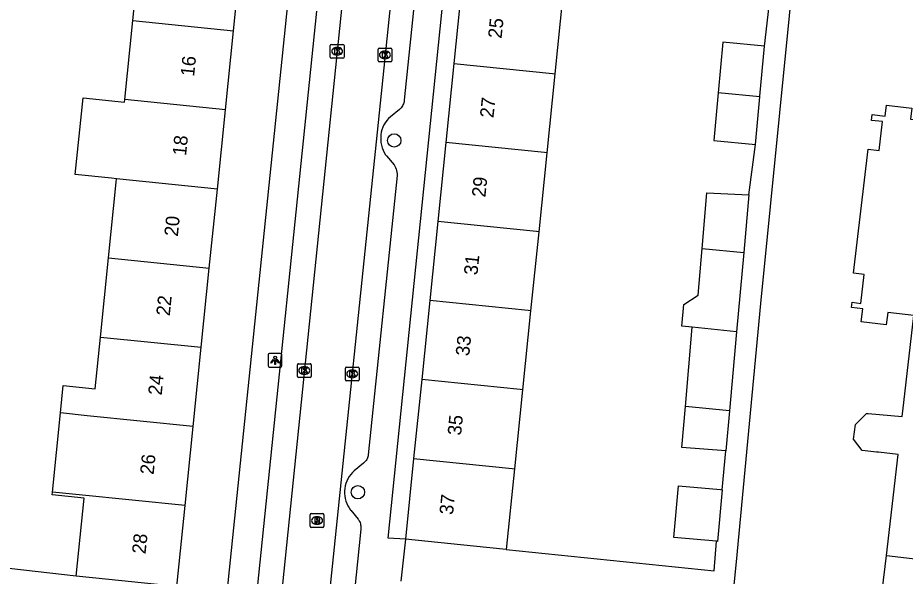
# Model space of a CAD drawing. Extents: x 160861 to 161308, y 384024 to 384878.
# Drawn here: x 161160.1 to 161224.9, y 384529.6 to 384570.4 of the extents above; entities that cross this region are included whole.
import ezdxf

# ---------------------------------------------------------------- set-up
doc = ezdxf.new("R2010")
doc.units = 0
for name, color, linetype in [('IMGEO_Boom', 7, 'Continuous'), ('IMGEO_Kolk', 7, 'Continuous'), ('IMGEO_Lichtpunt', 7, 'Continuous'), ('IMGEO_Pand', 7, 'Continuous'), ('IMGEO_Pand_nummerreeks', 7, 'Continuous'), ('IMGEO_Rijbaan_lokaal_open', 7, 'Continuous'), ('IMGEO_Rioolput', 7, 'Continuous'), ('IMGEO_Voetpad_open', 7, 'Continuous')]:
    doc.layers.add(name, color=color, linetype=linetype)

msp = doc.modelspace()

# ---------------------------------------------------------------- linework, layer by layer
at = {"layer": 'IMGEO_Boom'}
for centre in [(161187.565, 384561.474), (161184.912, 384535.755)]:
    msp.add_circle(centre, 0.489, dxfattribs=at)
at = {"layer": 'IMGEO_Kolk'}
for p, q in [((161182.898, 384567.567), (161182.898, 384568.419)), ((161182.973, 384568.493), (161183.825, 384568.493)), ((161183.386, 384568.273), (161183.411, 384568.273)), ((161183.899, 384568.419), (161183.899, 384567.567)), ((161186.386, 384567.299), (161186.386, 384568.151)), ((161186.461, 384568.225), (161187.313, 384568.225)), ((161186.874, 384568.005), (161186.899, 384568.005)), ((161187.387, 384568.151), (161187.387, 384567.299)), ((161183.825, 384567.493), (161182.973, 384567.493)), ((161183.409, 384567.713), (161183.384, 384567.713)), ((161186.897, 384567.445), (161186.872, 384567.445)), ((161187.313, 384567.225), (161186.461, 384567.225)), ((161180.495, 384544.229), (161180.495, 384545.081)), ((161180.57, 384545.155), (161181.422, 384545.155)), ((161180.983, 384544.935), (161181.008, 384544.935)), ((161181.496, 384545.081), (161181.496, 384544.229)), ((161183.996, 384543.983), (161183.996, 384544.835)), ((161184.071, 384544.909), (161184.923, 384544.909)), ((161184.484, 384544.689), (161184.509, 384544.689)), ((161184.997, 384544.835), (161184.997, 384543.983)), ((161181.422, 384544.155), (161180.57, 384544.155)), ((161181.006, 384544.375), (161180.981, 384544.375)), ((161184.507, 384544.129), (161184.482, 384544.129)), ((161184.923, 384543.909), (161184.071, 384543.909))]:
    msp.add_line(p, q, dxfattribs=at)
for points in [[(161182.898, 384567.567), (161182.898, 384568.419)], [(161182.973, 384568.493), (161183.825, 384568.493)], [(161183.219, 384568.193), (161183.342, 384568.193), (161183.342, 384568.042), (161183.472, 384568.193), (161183.636, 384568.193), (161183.49, 384568.042), (161183.643, 384567.793), (161183.491, 384567.793), (161183.406, 384567.957), (161183.342, 384567.89), (161183.342, 384567.793), (161183.219, 384567.793), (161183.219, 384568.193)], [(161183.899, 384568.419), (161183.899, 384567.567)], [(161186.386, 384567.299), (161186.386, 384568.151)], [(161186.461, 384568.225), (161187.313, 384568.225)], [(161187.387, 384568.151), (161187.387, 384567.299)], [(161183.825, 384567.493), (161182.973, 384567.493)], [(161186.707, 384567.925), (161186.83, 384567.925), (161186.83, 384567.774), (161186.96, 384567.925), (161187.124, 384567.925), (161186.978, 384567.774), (161187.131, 384567.525), (161186.979, 384567.525), (161186.894, 384567.689), (161186.83, 384567.622), (161186.83, 384567.525), (161186.707, 384567.525), (161186.707, 384567.925)], [(161187.313, 384567.225), (161186.461, 384567.225)], [(161180.495, 384544.229), (161180.495, 384545.081)], [(161180.57, 384545.155), (161181.422, 384545.155)], [(161180.816, 384544.855), (161180.939, 384544.855), (161180.939, 384544.704), (161181.069, 384544.855), (161181.233, 384544.855), (161181.087, 384544.704), (161181.24, 384544.455), (161181.088, 384544.455), (161181.003, 384544.619), (161180.939, 384544.552), (161180.939, 384544.455), (161180.816, 384544.455), (161180.816, 384544.855)], [(161181.496, 384545.081), (161181.496, 384544.229)], [(161183.996, 384543.983), (161183.996, 384544.835)], [(161184.071, 384544.909), (161184.923, 384544.909)], [(161184.997, 384544.835), (161184.997, 384543.983)], [(161181.422, 384544.155), (161180.57, 384544.155)], [(161184.317, 384544.609), (161184.44, 384544.609), (161184.44, 384544.458), (161184.57, 384544.609), (161184.734, 384544.609), (161184.588, 384544.458), (161184.741, 384544.209), (161184.589, 384544.209), (161184.504, 384544.373), (161184.44, 384544.306), (161184.44, 384544.209), (161184.317, 384544.209), (161184.317, 384544.609)], [(161184.923, 384543.909), (161184.071, 384543.909)]]:
    msp.add_lwpolyline(points, dxfattribs=at)
for centre, start, end in [((161182.975, 384568.417), 91.55205, 178.44795), ((161182.975, 384568.417), 91.55205, 178.44795), ((161183.823, 384568.417), 1.55205, 88.44795), ((161183.823, 384568.417), 1.55205, 88.44795), ((161186.463, 384568.149), 91.55205, 178.44795), ((161186.463, 384568.149), 91.55205, 178.44795), ((161187.311, 384568.149), 1.55205, 88.44795), ((161187.311, 384568.149), 1.55205, 88.44795), ((161182.975, 384567.569), 181.55205, 268.44795), ((161182.975, 384567.569), 181.55205, 268.44795), ((161183.823, 384567.569), 271.55205, 358.44795), ((161183.823, 384567.569), 271.55205, 358.44795), ((161186.463, 384567.301), 181.55205, 268.44795), ((161186.463, 384567.301), 181.55205, 268.44795), ((161187.311, 384567.301), 271.55205, 358.44795), ((161187.311, 384567.301), 271.55205, 358.44795), ((161180.572, 384545.079), 91.55205, 178.44795), ((161180.572, 384545.079), 91.55205, 178.44795), ((161181.42, 384545.079), 1.55205, 88.44795), ((161181.42, 384545.079), 1.55205, 88.44795), ((161184.073, 384544.833), 91.55205, 178.44795), ((161184.073, 384544.833), 91.55205, 178.44795), ((161184.921, 384544.833), 1.55205, 88.44795), ((161184.921, 384544.833), 1.55205, 88.44795), ((161180.572, 384544.231), 181.55205, 268.44795), ((161180.572, 384544.231), 181.55205, 268.44795), ((161181.42, 384544.231), 271.55205, 358.44795), ((161181.42, 384544.231), 271.55205, 358.44795), ((161184.073, 384543.985), 181.55205, 268.44795), ((161184.073, 384543.985), 181.55205, 268.44795), ((161184.921, 384543.985), 271.55205, 358.44795), ((161184.921, 384543.985), 271.55205, 358.44795)]:
    msp.add_arc(centre, 0.0765, start, end, dxfattribs=at)
for centre, major_axis, ratio, start_param, end_param in [((161183.385, 384567.993), (-0.387, 0.002), 0.722429, 4.712389, 7.853982), ((161183.41, 384567.993), (-0.39, 0.002), 0.717154, 1.570796, 4.712389), ((161186.873, 384567.725), (-0.387, 0.002), 0.722429, 4.712389, 7.853982), ((161186.898, 384567.725), (-0.39, 0.002), 0.717154, 1.570796, 4.712389), ((161180.982, 384544.655), (-0.387, 0.002), 0.722429, 4.712389, 7.853982), ((161181.007, 384544.655), (-0.39, 0.002), 0.717154, 1.570796, 4.712389), ((161184.483, 384544.409), (-0.387, 0.002), 0.722429, 4.712389, 7.853982), ((161184.508, 384544.409), (-0.39, 0.002), 0.717154, 1.570796, 4.712389)]:
    msp.add_ellipse(centre, major_axis=major_axis, ratio=ratio, start_param=start_param, end_param=end_param, dxfattribs=at)
at = {"layer": 'IMGEO_Lichtpunt'}
for p, q in [((161178.363, 384545.812), (161178.363, 384545.005)), ((161178.363, 384545.812), (161178.363, 384545.005)), ((161179.265, 384545.907), (161178.457, 384545.907)), ((161179.265, 384545.907), (161178.457, 384545.907)), ((161179.359, 384545.005), (161179.359, 384545.812)), ((161179.359, 384545.005), (161179.359, 384545.812)), ((161178.457, 384544.911), (161179.265, 384544.911)), ((161178.457, 384544.911), (161179.265, 384544.911))]:
    msp.add_line(p, q, dxfattribs=at)
for points in [[(161178.737, 384545.476), (161178.776, 384545.448), (161178.588, 384545.186), (161178.55, 384545.213), (161178.737, 384545.476)], [(161178.839, 384545.428), (161178.886, 384545.428), (161178.886, 384545.106), (161178.839, 384545.106), (161178.839, 384545.428)], [(161178.949, 384545.448), (161178.987, 384545.475), (161179.174, 384545.213), (161179.135, 384545.185), (161178.949, 384545.448)]]:
    msp.add_lwpolyline(points, dxfattribs=at)
msp.add_circle((161178.862, 384545.61), 0.0994, dxfattribs=at)
for centre, start, end in [((161178.457, 384545.812), 90, 180), ((161178.457, 384545.812), 90, 180), ((161179.265, 384545.812), 0, 90), ((161179.265, 384545.812), 0, 90), ((161178.457, 384545.005), 180, 270), ((161178.457, 384545.005), 180, 270), ((161179.265, 384545.005), 270, 0), ((161179.265, 384545.005), 270, 360)]:
    msp.add_arc(centre, 0.0946, start, end, dxfattribs=at)
at = {"layer": 'IMGEO_Pand'}
for points in [[(161168.464, 384570.248), (161169.053, 384576.035)], [(161175.822, 384569.5), (161176.41, 384575.287)], [(161192.519, 384572.886), (161191.929, 384567.109)], [(161199.89, 384572.134), (161199.301, 384566.357)], [(161167.876, 384564.461), (161168.464, 384570.248)], [(161168.464, 384570.248), (161175.822, 384569.5)], [(161225.533, 384548.667), (161223.624, 384548.891), (161223.52, 384548.001), (161221.688, 384548.215), (161221.799, 384549.171), (161220.972, 384549.268), (161221.016, 384549.64), (161221.66, 384549.565), (161221.906, 384551.675), (161221.133, 384551.765), (161222.192, 384560.826), (161222.989, 384560.733), (161223.236, 384562.851), (161222.433, 384562.945), (161222.482, 384563.366), (161223.433, 384563.255), (161223.527, 384564.055), (161225.384, 384563.838), (161225.291, 384563.038), (161227.162, 384562.819), (161227.455, 384565.319), (161229.097, 384565.127), (161229.684, 384570.142)], [(161175.234, 384563.713), (161175.822, 384569.5)], [(161214.608, 384568.376), (161211.574, 384568.651), (161211.239, 384564.944)], [(161214.272, 384564.67), (161214.276, 384564.709), (161214.608, 384568.376)], [(161191.929, 384567.109), (161191.34, 384561.331)], [(161191.929, 384567.109), (161199.133, 384566.374), (161199.301, 384566.357)], [(161199.301, 384566.357), (161198.712, 384560.579)], [(161211.239, 384564.944), (161210.924, 384561.464), (161213.957, 384561.189)], [(161214.272, 384564.67), (161211.239, 384564.944)], [(161167.288, 384558.673), (161166.911, 384558.711), (161164.259, 384558.98), (161164.83, 384564.59), (161167.858, 384564.283), (161167.876, 384564.461)], [(161175.234, 384563.713), (161167.876, 384564.461)], [(161213.957, 384561.189), (161214.272, 384564.67)], [(161174.645, 384557.925), (161175.234, 384563.713)], [(161191.34, 384561.331), (161190.751, 384555.554)], [(161198.712, 384560.579), (161198.543, 384560.596), (161191.34, 384561.331)], [(161198.712, 384560.579), (161198.122, 384554.802)], [(161166.699, 384552.886), (161167.263, 384558.427), (161167.288, 384558.673)], [(161174.645, 384557.925), (161167.288, 384558.673)], [(161174.057, 384552.138), (161174.645, 384557.925)], [(161210.057, 384553.584), (161210.396, 384557.64), (161213.484, 384557.505)], [(161213.484, 384557.505), (161213.101, 384553.273)], [(161190.751, 384555.554), (161190.162, 384549.777)], [(161198.122, 384554.802), (161197.953, 384554.819), (161190.751, 384555.554)], [(161198.122, 384554.802), (161197.533, 384549.025)], [(161209.342, 384547.819), (161208.572, 384547.898), (161208.732, 384549.47), (161209.771, 384550.16), (161210.057, 384553.584)], [(161210.057, 384553.584), (161213.101, 384553.273)], [(161213.101, 384553.273), (161212.578, 384547.49)], [(161166.111, 384547.099), (161166.699, 384552.886)], [(161166.699, 384552.886), (161174.057, 384552.138)], [(161173.469, 384546.351), (161174.057, 384552.138)], [(161190.162, 384549.777), (161189.573, 384544)], [(161197.533, 384549.025), (161197.364, 384549.042), (161190.162, 384549.777)], [(161197.533, 384549.025), (161196.944, 384543.248)], [(161223.524, 384531.132), (161224.387, 384538.506), (161222.958, 384538.674), (161222.792, 384538.693), (161221.75, 384538.815), (161221.131, 384539.643), (161221.264, 384540.699), (161222.067, 384541.519), (161222.196, 384541.508), (161224.679, 384541.297), (161224.697, 384541.516), (161224.717, 384541.685), (161225.533, 384548.667)], [(161208.858, 384542.031), (161209.342, 384547.819)], [(161212.578, 384547.49), (161209.342, 384547.819)], [(161212.578, 384547.49), (161212.054, 384541.705)], [(161163.178, 384541.55), (161163.383, 384543.562), (161165.727, 384543.324), (161166.111, 384547.099)], [(161166.111, 384547.099), (161173.469, 384546.351)], [(161172.881, 384540.564), (161173.469, 384546.351)], [(161189.573, 384544), (161188.983, 384538.222)], [(161196.944, 384543.248), (161196.774, 384543.265), (161189.573, 384544)], [(161196.944, 384543.248), (161196.355, 384537.47)], [(161162.59, 384535.762), (161163.178, 384541.55)], [(161172.881, 384540.564), (161165.146, 384541.35), (161163.178, 384541.55)], [(161211.789, 384538.778), (161208.586, 384539.029), (161208.858, 384542.031)], [(161212.054, 384541.705), (161208.858, 384542.031)], [(161212.054, 384541.705), (161211.789, 384538.778)], [(161172.292, 384534.776), (161172.881, 384540.564)], [(161188.983, 384538.222), (161188.382, 384532.327)], [(161188.983, 384538.222), (161196.184, 384537.487), (161196.355, 384537.47)], [(161196.355, 384537.47), (161195.754, 384531.575)], [(161211.113, 384532.169), (161207.991, 384532.451), (161208.332, 384536.226), (161211.409, 384535.947), (161211.532, 384535.936)], [(161164.334, 384529.618), (161164.914, 384535.328), (161162.57, 384535.566), (161162.59, 384535.762)], [(161172.292, 384534.776), (161164.557, 384535.562), (161162.59, 384535.762)], [(161211.532, 384535.936), (161211.19, 384532.162), (161211.113, 384532.169)], [(161171.692, 384528.87), (161172.292, 384534.776)], [(161195.754, 384531.575), (161193.357, 384531.82), (161188.382, 384532.327)], [(161221.41, 384513.788), (161222.273, 384521.163), (161220.783, 384521.337), (161220.714, 384521.345), (161219.719, 384521.461), (161219.123, 384522.244), (161219.282, 384523.324), (161220.046, 384524.258), (161220.19, 384524.242), (161222.685, 384523.95), (161222.707, 384524.142), (161223.009, 384526.722), (161223.524, 384531.132)], [(161223.524, 384531.132), (161235.341, 384529.749)], [(161171.692, 384528.87), (161166.718, 384529.376), (161164.334, 384529.618)]]:
    msp.add_lwpolyline(points, dxfattribs=at)
at = {"layer": 'IMGEO_Rijbaan_lokaal_open'}
for points in [[(161186.48, 384598.207), (161179.307, 384528.096), (161179.065, 384525.749)], [(161182.633, 384525.349), (161182.785, 384527.736), (161190.047, 384597.857)]]:
    msp.add_lwpolyline(points, dxfattribs=at)
at = {"layer": 'IMGEO_Rioolput'}
for p, q in [((161181.432, 384533.264), (161181.432, 384534.116)), ((161181.507, 384534.19), (161182.359, 384534.19)), ((161181.92, 384533.97), (161181.945, 384533.97)), ((161182.433, 384534.116), (161182.433, 384533.264)), ((161182.359, 384533.19), (161181.507, 384533.19)), ((161181.943, 384533.41), (161181.918, 384533.41))]:
    msp.add_line(p, q, dxfattribs=at)
for points in [[(161181.432, 384533.264), (161181.432, 384534.116)], [(161181.507, 384534.19), (161182.359, 384534.19)], [(161182.021, 384533.888), (161181.769, 384533.89), (161181.769, 384533.49)], [(161181.769, 384533.49), (161181.893, 384533.49), (161181.893, 384533.652), (161181.904, 384533.652)], [(161181.947, 384533.809), (161181.893, 384533.809), (161181.893, 384533.728)], [(161181.893, 384533.728), (161181.945, 384533.728)], [(161182.433, 384534.116), (161182.433, 384533.264)], [(161182.359, 384533.19), (161181.507, 384533.19)], [(161181.951, 384533.623), (161182.022, 384533.49), (161182.162, 384533.49), (161182.097, 384533.616)]]:
    msp.add_lwpolyline(points, dxfattribs=at)
for centre, radius, start, end in [((161181.509, 384534.114), 0.0765, 91.55205, 178.44795), ((161181.509, 384534.114), 0.0765, 91.55205, 178.44795), ((161181.903, 384533.599), 0.0533, 26.02933, 88.69889), ((161181.929, 384533.917), 0.19, 274.7715, 282.96867), ((161181.953, 384533.713), 0.0964, 77.00612, 93.18647), ((161181.967, 384533.77), 0.0378, 276.66336, 79.67722), ((161182.02, 384533.778), 0.109, 350.36119, 89.41601), ((161182.018, 384533.778), 0.112, 277.58423, 350.98172), ((161182.002, 384533.563), 0.108, 29.51342, 73.79051), ((161182.357, 384534.114), 0.0765, 1.55205, 88.44795), ((161182.357, 384534.114), 0.0765, 1.55205, 88.44795), ((161181.509, 384533.266), 0.0765, 181.55205, 268.44795), ((161181.509, 384533.266), 0.0765, 181.55205, 268.44795), ((161182.357, 384533.266), 0.0765, 271.55205, 358.44795), ((161182.357, 384533.266), 0.0765, 271.55205, 358.44795)]:
    msp.add_arc(centre, radius, start, end, dxfattribs=at)
for centre, major_axis, ratio, start_param, end_param in [((161181.919, 384533.69), (-0.387, 0.002), 0.722429, 4.712389, 7.853982), ((161181.944, 384533.69), (-0.39, 0.002), 0.717154, 1.570796, 4.712389)]:
    msp.add_ellipse(centre, major_axis=major_axis, ratio=ratio, start_param=start_param, end_param=end_param, dxfattribs=at)
at = {"layer": 'IMGEO_Voetpad_open'}
for points in [[(161185.695, 384432.994), (161189.991, 384439.907), (161201.696, 384458.913), (161203.982, 384463.225), (161205.809, 384471.484), (161207.136, 384481.547), (161208.737, 384497.685), (161211.066, 384515.775), (161212.573, 384530.677), (161214.362, 384549.557), (161218.539, 384591.638), (161224.003, 384644.44)], [(161183.719, 384609.738), (161175.337, 384528.423), (161171.692, 384528.87)], [(161190.736, 384587.948), (161188.295, 384564.431), (161188.293, 384564.393), (161188.282, 384564.31), (161188.264, 384564.229), (161188.239, 384564.15), (161188.207, 384564.073), (161188.168, 384563.999), (161188.123, 384563.929), (161188.071, 384563.864), (161188.014, 384563.803), (161187.952, 384563.748), (161187.284, 384563.208), (161187.148, 384563.075), (161187.024, 384562.93), (161186.914, 384562.774), (161186.819, 384562.609), (161186.738, 384562.437), (161186.673, 384562.258), (161186.624, 384562.073), (161186.592, 384561.885), (161186.577, 384561.696), (161186.579, 384561.505), (161186.598, 384561.315), (161186.634, 384561.128), (161186.686, 384560.945), (161186.755, 384560.767), (161186.839, 384560.596), (161186.938, 384560.433), (161187.002, 384560.343), (161187.558, 384559.689), (161187.612, 384559.598), (161187.664, 384559.493), (161187.707, 384559.383), (161187.739, 384559.269), (161187.761, 384559.153), (161187.773, 384559.036), (161187.774, 384558.918), (161185.665, 384538.48), (161185.656, 384538.408), (161185.641, 384538.338), (161185.619, 384538.269), (161185.592, 384538.202), (161185.558, 384538.138), (161185.519, 384538.077), (161185.474, 384538.02), (161185.425, 384537.967), (161185.371, 384537.918), (161185.313, 384537.875), (161184.649, 384537.322), (161184.514, 384537.193), (161184.391, 384537.053), (161184.28, 384536.902), (161184.184, 384536.742), (161184.103, 384536.574), (161184.036, 384536.4), (161183.986, 384536.22), (161183.952, 384536.036), (161183.934, 384535.85), (161183.933, 384535.664), (161183.949, 384535.478), (161183.982, 384535.294), (161184.03, 384535.113), (161184.095, 384534.938), (161184.175, 384534.77), (161184.269, 384534.609), (161184.378, 384534.457), (161184.393, 384534.438), (161184.923, 384533.789), (161184.953, 384533.75), (161184.999, 384533.681), (161185.038, 384533.609), (161185.07, 384533.534), (161185.096, 384533.456), (161185.114, 384533.376), (161185.126, 384533.295), (161185.13, 384533.213), (161185.127, 384533.131), (161185.116, 384533.05), (161184.533, 384527.339)], [(161188.382, 384532.327), (161187.135, 384532.404), (161192.466, 384584.685)], [(161214.608, 384568.376), (161215.099, 384572.607)], [(161177.513, 384528.033), (161181.919, 384570.937)], [(161213.484, 384557.505), (161213.957, 384561.189)], [(161211.532, 384535.936), (161211.789, 384538.778)], [(161188.382, 384532.327), (161188.217, 384530.792), (161188.052, 384529.256)], [(161195.754, 384531.575), (161210.945, 384530.022), (161211.113, 384532.169)], [(161164.334, 384529.618), (161148.694, 384531.411)]]:
    msp.add_lwpolyline(points, dxfattribs=at)

# ---------------------------------------------------------------- texts
at = {"layer": 'IMGEO_Pand_nummerreeks'}
for s, rotation, p in [('25', 84.17658, (161195.408, 384568.894)), ('16', 84.19588, (161172.945, 384566.121)), ('27', 84.17658, (161194.816, 384563.091)), ('18', 84.19615, (161172.356, 384560.32)), ('29', 84.17658, (161194.225, 384557.287)), ('20', 84.19615, (161171.756, 384554.425)), ('31', 84.17658, (161193.644, 384551.596)), ('22', 84.19588, (161171.166, 384548.614)), ('33', 84.17658, (161193.041, 384545.68)), ('24', 84.19588, (161170.576, 384542.813)), ('35', 84.17658, (161192.449, 384539.877)), ('26', 84.19588, (161169.986, 384537.009)), ('37', 84.17658, (161191.857, 384534.073)), ('28', 84.19588, (161169.396, 384531.207))]:
    msp.add_text(s, height=1, rotation=rotation, dxfattribs=at).set_placement(p)

doc.saveas('drawing.dxf')
